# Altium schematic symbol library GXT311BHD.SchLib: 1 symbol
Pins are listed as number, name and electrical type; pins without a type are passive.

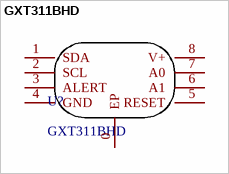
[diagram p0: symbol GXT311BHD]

## GXT311BHD
designator U?
footprint DFN-8-EP_L3.0-W3.0-P0.65
pins: 0 EP, 1 SDA, 2 SCL, 3 ALERT, 4 GND, 5 RESET, 6 A1, 7 A0, 8 V+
